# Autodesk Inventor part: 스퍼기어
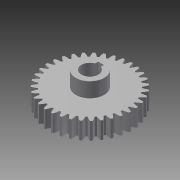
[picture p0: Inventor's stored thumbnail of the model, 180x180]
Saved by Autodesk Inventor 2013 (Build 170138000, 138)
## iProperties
Created: 2013-08
Part Number: 스퍼기어
Material: 강
Document SubType Name: Modeling
Designer: 한국산업디자인학원
Categories: <?xml version="1.0" encoding="UTF-16"?> <MemberInstance><Categories><FamilyTemplate><FamilyTemplateParameter ValueType="xs:double" Id="1" ObjectReferenceKey="da
Density: 1 g/cm^3
CustomPartVersion: 1
Author: 한국산업디자인학원
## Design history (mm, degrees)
sketch "Sketch1"
  geometry: C1 r 37 at (0, 0)
  constraints: 1 centre point
  dimensions: "d0" = 74 diameter of C1 (= da_da)
extrude "Extrusion1" new body sketch "Sketch1" distance "d1" = 15 (= da_b); taper "d2" = 0 deg
workplane "Work Plane2"
feature "피치 지름" dims "d4" = 10, "d5" = 0
workplane "Work Plane8"
workplane "Work Plane9"
feature "스퍼 기어" dims "da_b" = 15, "da_d" = 70, "da_aw" = 70, "da_da" = 74, "da_df" = 65, "da_dw" = 70, angle "da_beta" = 0 deg, "da_lefttooth" = 0, "da_righttooth" = 0
sketch "스케치3"
  geometry: C1 r 12.5 at (0, 0); A1 r 37 centre (0, 0) between (-5.788, 36.544) and (-7.422, 36.248) reference
  constraints: 1 centre point, 1 coincident
  dimensions: "d49" = 25 diameter of C1
extrude "돌출2" join sketch "스케치3" distance "d51" = 13; taper "d52" = 0 deg
sketch "스케치4"
  geometry: C1 r 12.5 at (0, 0); A1 r 32.5 centre (0, 0) between (9.347, 31.127) and (7.941, 31.515) reference
  constraints: 1 centre point, 1 coincident
  dimensions: "d53" = 25 diameter of C1
extrude "돌출3" join sketch "스케치4" distance "d55" = 3; taper "d56" = 0 deg
sketch "스케치5"
  geometry: C1 r 12.5 at (0, 0) reference; 1 further point
  constraints: 1 coincident
hole "구멍1" sketch "스케치5" at (0, 0) diameter "d57" = 15; stored, may be unused: countersink angle "d61" = 90 deg, drill point angle "d63" = 0 deg; dims "d58" = 6, "d59" = 4, "d60" = 2, "d62" = 31
sketch "스케치6"
  geometry: L1 (-2.5, 9.8)-(2.5, 9.8); L2 (2.5, 9.8)-(2.5, 0); L3 (2.5, 0)-(-2.5, 0); L4 (-2.5, 0)-(-2.5, 9.8); C1 r 7.5 at (0, 0) reference; 1 further point
  constraints: 8 end point, 2 parallel, 1 coincident, 1 horizontal, 1 midpoint, 1 perpendicular
  dimensions: "d64" = 9.8 distance between parallel lines of L3 L1; "d66" = 5 distance of L1.start L1.end
extrude "돌출4" cut sketch "스케치6" distance "d67" = 31; taper "d68" = 0 deg
body "Solid1"
sketch "Sketch2"
  geometry: C1 r 37 at (0, 0) reference; C2 r 35 at (0, 0)
  constraints: 1 centre point, 1 coincident
  dimensions: "d3" = 70 diameter of C2 (= da_dw)
body "Srf1"
other parameters: "d17" = 0, "d34" = 0.8976 (computed from da_z), "d39" = 0, "d41" = 0, "d47" = 0, "d48" = 0
